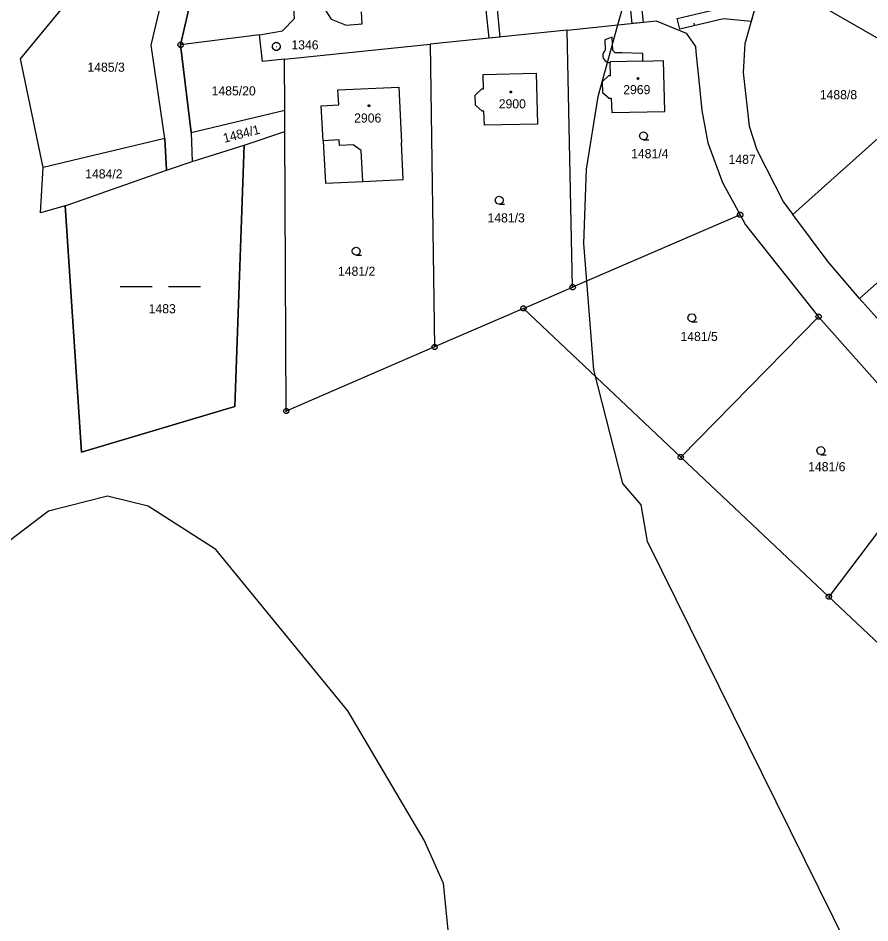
# Model space of a CAD drawing. Extents: x -779618 to -776429, y -1144546 to -1143350.
# Drawn here: x -777658 to -777499.3, y -1144217.4 to -1144048.7 of the extents above; entities that cross this region are included whole.
import ezdxf

# ---------------------------------------------------------------- set-up
doc = ezdxf.new("R2010")
doc.units = 0
for name, color, linetype in [('1', 7, 'Continuous'), ('11', 7, 'Continuous'), ('12', 7, 'Continuous'), ('13', 7, 'Continuous'), ('2', 7, 'Continuous'), ('3', 7, 'Continuous'), ('4', 7, 'Continuous'), ('5', 7, 'Continuous'), ('8', 7, 'Continuous')]:
    doc.layers.add(name, color=color, linetype=linetype)

msp = doc.modelspace()

# ---------------------------------------------------------------- linework, layer by layer
at = {"layer": '1'}
for p, q in [((-777657.54, -1144056.3), (-777632.39, -1144025.74)), ((-777633.19, -1144053.78), (-777629.33, -1144037.46)), ((-777627.73, -1144053.71), (-777624.08, -1144037.74)), ((-777485.15, -1144059.78), (-777518.65, -1144040.52)), ((-777606.52, -1144048.78), (-777606.82, -1144043.8)), ((-777520.17, -1144044.8), (-777522.59, -1144053.51)), ((-777600.8, -1144047.19), (-777599.69, -1144048.93)), ((-777593.88, -1144049.82), (-777594.01, -1144047.57)), ((-777608.75, -1144051.12), (-777606.52, -1144048.78)), ((-777599.69, -1144048.93), (-777596.89, -1144050.06)), ((-777596.89, -1144050.06), (-777593.88, -1144049.82)), ((-777555.7, -1144050.96), (-777539.11, -1144049.26)), ((-777539.11, -1144049.26), (-777533.56, -1144051.53)), ((-777613, -1144051.82), (-777627.73, -1144053.71)), ((-777613, -1144051.82), (-777608.75, -1144051.12)), ((-777612.48, -1144056.79), (-777613, -1144051.82)), ((-777555.7, -1144050.96), (-777581.22, -1144053.58)), ((-777554.68, -1144098.88), (-777555.7, -1144050.96)), ((-777533.56, -1144051.53), (-777531.81, -1144054.01)), ((-777547.29, -1144052.3), (-777548.69, -1144052.78)), ((-777548.69, -1144052.78), (-777548.61, -1144054.74)), ((-777547.17, -1144054.77), (-777547.29, -1144052.3)), ((-777522.59, -1144053.51), (-777522.93, -1144058.88)), ((-777630.64, -1144071.16), (-777633.19, -1144053.78)), ((-777625.77, -1144070.02), (-777627.73, -1144053.71)), ((-777608.35, -1144056.36), (-777581.22, -1144053.58)), ((-777581.22, -1144053.58), (-777580.41, -1144110.01)), ((-777546.79, -1144055.22), (-777547.17, -1144054.77)), ((-777545.5, -1144055.19), (-777546.79, -1144055.22)), ((-777541.62, -1144055.29), (-777545.5, -1144055.19)), ((-777531.81, -1144054.01), (-777531.72, -1144055)), ((-777531.72, -1144055), (-777531, -1144062.14)), ((-777653.31, -1144076.59), (-777657.54, -1144056.3)), ((-777608.35, -1144056.36), (-777612.48, -1144056.79)), ((-777608.31, -1144065.88), (-777608.35, -1144056.36)), ((-777541.58, -1144056.72), (-777541.62, -1144055.29)), ((-777541.58, -1144056.72), (-777537.78, -1144056.61)), ((-777537.5, -1144066.1), (-777537.78, -1144056.61)), ((-777547.6, -1144059.49), (-777547.68, -1144056.99)), ((-777571.35, -1144059.22), (-777561.47, -1144058.99)), ((-777571.32, -1144061.92), (-777571.35, -1144059.22)), ((-777561.47, -1144058.99), (-777561.24, -1144068.47)), ((-777548, -1144059.51), (-777549.17, -1144060.63)), ((-777547.6, -1144059.49), (-777548, -1144059.51)), ((-777522.93, -1144058.88), (-777521.8, -1144068.84)), ((-777485.15, -1144059.78), (-777513.67, -1144085.31)), ((-777572.83, -1144063.08), (-777571.63, -1144061.93)), ((-777571.63, -1144061.93), (-777571.32, -1144061.92)), ((-777549.17, -1144060.63), (-777549.11, -1144062.6)), ((-777572.79, -1144064.95), (-777572.83, -1144063.08)), ((-777549.11, -1144062.6), (-777547.86, -1144063.66)), ((-777547.86, -1144063.66), (-777547.49, -1144063.65)), ((-777547.49, -1144063.65), (-777547.41, -1144066.34)), ((-777531, -1144062.14), (-777530.62, -1144065.92)), ((-777571.53, -1144066.04), (-777572.79, -1144064.95)), ((-777625.77, -1144070.02), (-777608.31, -1144065.88)), ((-777608.29, -1144069.84), (-777608.31, -1144065.88)), ((-777571.2, -1144066.04), (-777571.53, -1144066.04)), ((-777571.12, -1144068.69), (-777571.2, -1144066.04)), ((-777547.41, -1144066.34), (-777537.5, -1144066.1)), ((-777530.62, -1144065.92), (-777529.5, -1144071.94)), ((-777561.24, -1144068.47), (-777571.12, -1144068.69)), ((-777625.77, -1144070.02), (-777625.56, -1144075.42)), ((-777615.88, -1144072.39), (-777608.29, -1144069.84)), ((-777608.03, -1144121.95), (-777608.29, -1144069.84)), ((-777521.8, -1144068.84), (-777520.37, -1144073.26)), ((-777630.64, -1144071.16), (-777653.31, -1144076.59)), ((-777630.64, -1144071.16), (-777630.34, -1144077.09)), ((-777529.5, -1144071.94), (-777526.76, -1144079.38)), ((-777625.56, -1144075.42), (-777615.88, -1144072.39)), ((-777617.61, -1144121.09), (-777615.88, -1144072.39)), ((-777520.37, -1144073.26), (-777515.39, -1144083)), ((-777630.34, -1144077.09), (-777625.56, -1144075.42)), ((-777653.82, -1144085.01), (-777653.31, -1144076.59)), ((-777649.25, -1144083.72), (-777630.34, -1144077.09)), ((-777526.76, -1144079.38), (-777523.47, -1144085.39)), ((-777649.25, -1144083.72), (-777653.82, -1144085.01)), ((-777649.25, -1144083.72), (-777646.16, -1144129.59)), ((-777515.39, -1144083), (-777513.67, -1144085.31)), ((-777523.47, -1144085.39), (-777554.68, -1144098.88)), ((-777523.47, -1144085.39), (-777522.46, -1144087.24)), ((-777507.1, -1144094.15), (-777513.67, -1144085.31)), ((-777522.46, -1144087.24), (-777508.85, -1144104.39)), ((-777501.24, -1144101.01), (-777484.5, -1144086.12)), ((-777501.24, -1144101.01), (-777507.1, -1144094.15)), ((-777563.85, -1144102.85), (-777554.68, -1144098.88)), ((-777495.19, -1144107.76), (-777501.24, -1144101.01)), ((-777563.85, -1144102.85), (-777580.41, -1144110.01)), ((-777534.53, -1144130.54), (-777563.85, -1144102.85)), ((-777508.85, -1144104.39), (-777534.53, -1144130.54)), ((-777486.58, -1144129.52), (-777508.85, -1144104.39)), ((-777580.41, -1144110.01), (-777608.03, -1144121.95)), ((-777646.16, -1144129.59), (-777617.61, -1144121.09)), ((-777534.53, -1144130.54), (-777506.95, -1144156.58)), ((-777486.58, -1144129.52), (-777506.95, -1144156.58)), ((-777506.95, -1144156.58), (-777482.03, -1144180.11))]:
    msp.add_line(p, q, dxfattribs=at)
for points in [[(-777548.61, -1144054.74), (-777548.82, -1144054.95), (-777548.98, -1144055.24), (-777549.06, -1144055.56), (-777549.06, -1144055.89), (-777548.98, -1144056.18), (-777548.84, -1144056.45), (-777548.61, -1144056.71), (-777548.32, -1144056.89), (-777547.99, -1144056.99), (-777547.68, -1144056.99)], [(-777598.43, -1144062.06), (-777587.08, -1144061.59), (-777586.58, -1144071.89)], [(-777601.18, -1144071.59), (-777601.53, -1144065.06), (-777598.26, -1144064.89), (-777598.43, -1144062.06)], [(-777601.18, -1144071.59), (-777600.74, -1144079.5), (-777593.77, -1144079.18)], [(-777593.77, -1144079.18), (-777586.24, -1144078.81), (-777586.58, -1144071.89)]]:
    msp.add_lwpolyline(points, dxfattribs=at)
at = {"layer": '11'}
for points in [[(-777624.08, -1144037.74), (-777627.73, -1144053.71), (-777625.77, -1144070.02), (-777625.56, -1144075.42), (-777615.88, -1144072.39), (-777617.61, -1144121.09), (-777646.16, -1144129.59), (-777649.25, -1144083.72), (-777630.34, -1144077.09), (-777630.64, -1144071.16), (-777653.31, -1144076.59), (-777657.54, -1144056.3), (-777632.39, -1144025.74)], [(-777500.75, -1144227.2), (-777540.73, -1144146.25), (-777541.9, -1144139.45), (-777545.31, -1144135.44), (-777550.75, -1144114.29), (-777552.59, -1144090.73), (-777552.11, -1144076.87), (-777549.94, -1144063.31), (-777546.24, -1144049.99), (-777544.16, -1144042.52)], [(-777673.02, -1144362.58), (-777656.01, -1144347.08), (-777622.27, -1144320.95), (-777616.12, -1144317.31), (-777606.33, -1144308.72), (-777602.78, -1144305.6), (-777600.94, -1144303.98), (-777587.46, -1144285.76), (-777578.63, -1144256.7), (-777576.43, -1144232.95), (-777578.73, -1144210.01), (-777582.32, -1144201.96), (-777596.56, -1144177.86), (-777621.13, -1144147.79), (-777633.74, -1144139.7), (-777641.37, -1144137.83), (-777652.35, -1144140.64), (-777669.76, -1144153.87)]]:
    msp.add_lwpolyline(points, dxfattribs=at)
at = {"layer": '12'}
for p, q in [((-777541.58, -1144056.72), (-777547.68, -1144056.89)), ((-777547.68, -1144056.89), (-777547.68, -1144056.99)), ((-777541.58, -1144056.72), (-777537.78, -1144056.61)), ((-777537.5, -1144066.1), (-777537.78, -1144056.61)), ((-777547.6, -1144059.49), (-777547.68, -1144056.99)), ((-777571.35, -1144059.22), (-777561.47, -1144058.99)), ((-777571.32, -1144061.92), (-777571.35, -1144059.22)), ((-777561.47, -1144058.99), (-777561.24, -1144068.47)), ((-777548, -1144059.51), (-777549.17, -1144060.63)), ((-777547.6, -1144059.49), (-777548, -1144059.51)), ((-777572.83, -1144063.08), (-777571.63, -1144061.93)), ((-777571.63, -1144061.93), (-777571.32, -1144061.92)), ((-777549.17, -1144060.63), (-777549.11, -1144062.6)), ((-777572.79, -1144064.95), (-777572.83, -1144063.08)), ((-777549.11, -1144062.6), (-777547.86, -1144063.66)), ((-777547.86, -1144063.66), (-777547.49, -1144063.65)), ((-777547.49, -1144063.65), (-777547.41, -1144066.34)), ((-777571.53, -1144066.04), (-777572.79, -1144064.95)), ((-777571.2, -1144066.04), (-777571.53, -1144066.04)), ((-777571.12, -1144068.69), (-777571.2, -1144066.04)), ((-777547.41, -1144066.34), (-777537.5, -1144066.1)), ((-777561.24, -1144068.47), (-777571.12, -1144068.69))]:
    msp.add_line(p, q, dxfattribs=at)
for points in [[(-777598.43, -1144062.06), (-777587.08, -1144061.59), (-777586.58, -1144071.89)], [(-777601.18, -1144071.59), (-777601.53, -1144065.06), (-777598.26, -1144064.89), (-777598.43, -1144062.06)], [(-777593.77, -1144079.18), (-777594.06, -1144073.38), (-777595.58, -1144072.33), (-777598.09, -1144072.45), (-777598.17, -1144071.44), (-777601.18, -1144071.59)], [(-777593.77, -1144079.18), (-777586.24, -1144078.81), (-777586.58, -1144071.89)]]:
    msp.add_lwpolyline(points, dxfattribs=at)
at = {"layer": '13'}
for p, q in [((-777543.58, -1144049.72), (-777544.12, -1144044.4)), ((-777542.1, -1144044.19), (-777541.56, -1144049.51)), ((-777570.23, -1144052.45), (-777570.77, -1144047.25)), ((-777568.77, -1144047.04), (-777568.24, -1144052.25)), ((-777535.18, -1144048.8), (-777526.74, -1144046.83)), ((-777520.87, -1144047.34), (-777521.43, -1144049.33)), ((-777541.56, -1144049.51), (-777543.58, -1144049.72)), ((-777534.72, -1144050.78), (-777535.18, -1144048.8)), ((-777526.6, -1144048.88), (-777534.72, -1144050.78)), ((-777531.96, -1144050.13), (-777532.07, -1144049.65)), ((-777521.43, -1144049.33), (-777526.6, -1144048.88)), ((-777568.24, -1144052.25), (-777570.23, -1144052.45))]:
    msp.add_line(p, q, dxfattribs=at)
at = {"layer": '3'}
for p, q in [((-777639, -1144098.75), (-777633, -1144098.75)), ((-777630, -1144098.75), (-777624, -1144098.75))]:
    msp.add_line(p, q, dxfattribs=at)
for points in [[(-777541.48, -1144071.41), (-777541.86, -1144071.31), (-777542.13, -1144071.04), (-777542.23, -1144070.67), (-777542.13, -1144070.3), (-777541.86, -1144070.03), (-777541.49, -1144069.93), (-777541.12, -1144070.03), (-777540.85, -1144070.3), (-777540.75, -1144070.68), (-777540.85, -1144071.06), (-777541.12, -1144071.33), (-777541.5, -1144071.43), (-777540.5, -1144071.43)], [(-777568.34, -1144083.41), (-777568.72, -1144083.31), (-777568.99, -1144083.04), (-777569.09, -1144082.67), (-777568.99, -1144082.3), (-777568.72, -1144082.03), (-777568.35, -1144081.93), (-777567.98, -1144082.03), (-777567.71, -1144082.3), (-777567.61, -1144082.68), (-777567.71, -1144083.06), (-777567.98, -1144083.33), (-777568.36, -1144083.43), (-777567.36, -1144083.43)], [(-777595.02, -1144092.9), (-777595.4, -1144092.8), (-777595.67, -1144092.53), (-777595.77, -1144092.16), (-777595.67, -1144091.79), (-777595.4, -1144091.52), (-777595.03, -1144091.42), (-777594.66, -1144091.52), (-777594.39, -1144091.79), (-777594.29, -1144092.17), (-777594.39, -1144092.55), (-777594.66, -1144092.82), (-777595.04, -1144092.92), (-777594.04, -1144092.92)], [(-777532.47, -1144105.3), (-777532.85, -1144105.2), (-777533.12, -1144104.93), (-777533.22, -1144104.56), (-777533.12, -1144104.19), (-777532.85, -1144103.92), (-777532.48, -1144103.82), (-777532.11, -1144103.92), (-777531.84, -1144104.19), (-777531.74, -1144104.57), (-777531.84, -1144104.95), (-777532.11, -1144105.22), (-777532.49, -1144105.32), (-777531.49, -1144105.32)], [(-777508.44, -1144130.07), (-777508.82, -1144129.97), (-777509.09, -1144129.7), (-777509.19, -1144129.33), (-777509.09, -1144128.96), (-777508.82, -1144128.69), (-777508.45, -1144128.59), (-777508.08, -1144128.69), (-777507.81, -1144128.96), (-777507.71, -1144129.34), (-777507.81, -1144129.72), (-777508.08, -1144129.99), (-777508.46, -1144130.09), (-777507.46, -1144130.09)]]:
    msp.add_lwpolyline(points, dxfattribs=at)
at = {"layer": '4'}
for p, q in [((-777541.58, -1144056.72), (-777547.68, -1144056.89)), ((-777547.68, -1144056.89), (-777547.68, -1144056.99))]:
    msp.add_line(p, q, dxfattribs=at)
msp.add_lwpolyline([(-777593.77, -1144079.18), (-777594.06, -1144073.38), (-777595.58, -1144072.33), (-777598.09, -1144072.45), (-777598.17, -1144071.44), (-777601.18, -1144071.59)], dxfattribs=at)
at = {"layer": '5'}
for points in [[(-777542.54, -1144059.82), (-777542.44, -1144059.84), (-777542.39, -1144059.93), (-777542.37, -1144059.99), (-777542.39, -1144060.08), (-777542.47, -1144060.15), (-777542.54, -1144060.16), (-777542.63, -1144060.13), (-777542.69, -1144060.07), (-777542.71, -1144059.99), (-777542.69, -1144059.9), (-777542.61, -1144059.83)], [(-777566.2, -1144062.33), (-777566.1, -1144062.35), (-777566.05, -1144062.44), (-777566.03, -1144062.5), (-777566.05, -1144062.59), (-777566.13, -1144062.66), (-777566.2, -1144062.67), (-777566.29, -1144062.64), (-777566.35, -1144062.58), (-777566.37, -1144062.5), (-777566.35, -1144062.41), (-777566.27, -1144062.34)], [(-777592.62, -1144064.87), (-777592.52, -1144064.89), (-777592.47, -1144064.98), (-777592.45, -1144065.04), (-777592.47, -1144065.13), (-777592.55, -1144065.2), (-777592.62, -1144065.21), (-777592.71, -1144065.18), (-777592.77, -1144065.12), (-777592.79, -1144065.04), (-777592.77, -1144064.95), (-777592.69, -1144064.88)]]:
    msp.add_lwpolyline(points, close=True, dxfattribs=at)
at = {"layer": '8'}
for p, q in [((-777627.85, -1144053.71), (-777627.61, -1144053.71)), ((-777609.94, -1144054), (-777609.84, -1144054)), ((-777523.59, -1144085.39), (-777523.35, -1144085.39)), ((-777554.8, -1144098.88), (-777554.56, -1144098.88)), ((-777563.97, -1144102.85), (-777563.73, -1144102.85)), ((-777508.97, -1144104.39), (-777508.73, -1144104.39)), ((-777580.53, -1144110.01), (-777580.29, -1144110.01)), ((-777608.15, -1144121.95), (-777607.91, -1144121.95)), ((-777534.65, -1144130.54), (-777534.41, -1144130.54)), ((-777507.07, -1144156.58), (-777506.83, -1144156.58))]:
    msp.add_line(p, q, dxfattribs=at)
for points in [[(-777627.58, -1144053.23), (-777627.33, -1144053.41), (-777627.23, -1144053.7), (-777627.33, -1144053.99), (-777627.58, -1144054.17), (-777627.89, -1144054.17), (-777628.14, -1144053.99), (-777628.24, -1144053.7), (-777628.14, -1144053.41), (-777627.89, -1144053.23)], [(-777609.7, -1144053.28), (-777609.36, -1144053.47), (-777609.17, -1144053.81), (-777609.17, -1144054.2), (-777609.36, -1144054.54), (-777609.7, -1144054.73), (-777610.09, -1144054.73), (-777610.43, -1144054.54), (-777610.62, -1144054.2), (-777610.62, -1144053.81), (-777610.43, -1144053.47), (-777610.09, -1144053.28)], [(-777523.32, -1144084.91), (-777523.07, -1144085.09), (-777522.97, -1144085.38), (-777523.07, -1144085.67), (-777523.32, -1144085.85), (-777523.63, -1144085.85), (-777523.88, -1144085.67), (-777523.98, -1144085.38), (-777523.88, -1144085.09), (-777523.63, -1144084.91)], [(-777554.53, -1144098.4), (-777554.28, -1144098.58), (-777554.18, -1144098.87), (-777554.28, -1144099.16), (-777554.53, -1144099.34), (-777554.84, -1144099.34), (-777555.09, -1144099.16), (-777555.19, -1144098.87), (-777555.09, -1144098.58), (-777554.84, -1144098.4)], [(-777563.7, -1144102.37), (-777563.45, -1144102.55), (-777563.35, -1144102.84), (-777563.45, -1144103.13), (-777563.7, -1144103.31), (-777564.01, -1144103.31), (-777564.26, -1144103.13), (-777564.36, -1144102.84), (-777564.26, -1144102.55), (-777564.01, -1144102.37)], [(-777508.7, -1144103.91), (-777508.45, -1144104.09), (-777508.35, -1144104.38), (-777508.45, -1144104.67), (-777508.7, -1144104.85), (-777509.01, -1144104.85), (-777509.26, -1144104.67), (-777509.36, -1144104.38), (-777509.26, -1144104.09), (-777509.01, -1144103.91)], [(-777580.26, -1144109.53), (-777580.01, -1144109.71), (-777579.91, -1144110), (-777580.01, -1144110.29), (-777580.26, -1144110.47), (-777580.57, -1144110.47), (-777580.82, -1144110.29), (-777580.92, -1144110), (-777580.82, -1144109.71), (-777580.57, -1144109.53)], [(-777607.88, -1144121.47), (-777607.63, -1144121.65), (-777607.53, -1144121.94), (-777607.63, -1144122.23), (-777607.88, -1144122.41), (-777608.19, -1144122.41), (-777608.44, -1144122.23), (-777608.54, -1144121.94), (-777608.44, -1144121.65), (-777608.19, -1144121.47)], [(-777534.38, -1144130.06), (-777534.13, -1144130.24), (-777534.03, -1144130.53), (-777534.13, -1144130.82), (-777534.38, -1144131), (-777534.69, -1144131), (-777534.94, -1144130.82), (-777535.04, -1144130.53), (-777534.94, -1144130.24), (-777534.69, -1144130.06)], [(-777506.8, -1144156.1), (-777506.55, -1144156.28), (-777506.45, -1144156.57), (-777506.55, -1144156.86), (-777506.8, -1144157.04), (-777507.11, -1144157.04), (-777507.36, -1144156.86), (-777507.46, -1144156.57), (-777507.36, -1144156.28), (-777507.11, -1144156.1)]]:
    msp.add_lwpolyline(points, close=True, dxfattribs=at)

# ---------------------------------------------------------------- texts
at = {"layer": '2'}
for s, p in [('1485/3', (-777645.08, -1144058.72)), ('1485/20', (-777621.94, -1144063.13)), ('2969', (-777545.26, -1144062.9)), ('1488/8', (-777508.64, -1144063.85)), ('2900', (-777568.45, -1144065.55)), ('2906', (-777595.39, -1144068.19)), ('1481/4', (-777543.79, -1144074.83)), ('1487', (-777525.63, -1144075.9)), ('1484/2', (-777645.5, -1144078.61)), ('1481/3', (-777570.55, -1144086.8)), ('1481/2', (-777598.4, -1144096.75)), ('1483', (-777633.67, -1144103.74)), ('1481/5', (-777534.6, -1144108.9)), ('1481/6', (-777510.81, -1144133.18))]:
    msp.add_text(s, height=1.7, dxfattribs=at).set_placement(p)
msp.add_text('1484/1', height=1.7, rotation=14.4958, dxfattribs=at).set_placement((-777619.56, -1144071.97))
at = {"layer": '8'}
msp.add_text('1346', height=1.7, dxfattribs=at).set_placement((-777607.08, -1144054.56))

doc.saveas('drawing.dxf')
